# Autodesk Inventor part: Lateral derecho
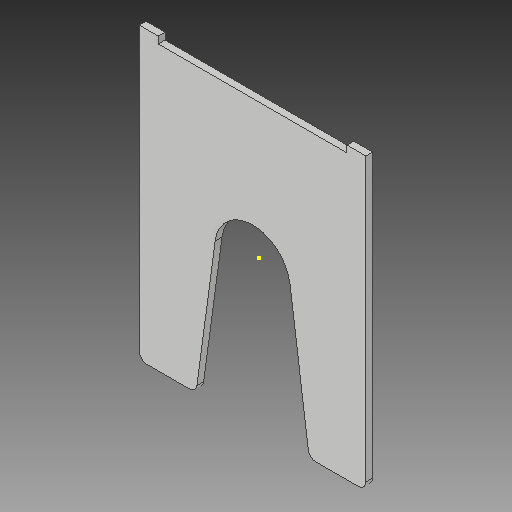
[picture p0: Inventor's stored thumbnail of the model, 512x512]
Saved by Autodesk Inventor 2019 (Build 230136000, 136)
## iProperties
Created: 2019-02
Part Number: Lateral derecho
Material: Genérico
Document SubType Name: Modeling
Designer: Juan Manuel Montalvo Navarrete
Density: 1 g/cm^3
Appearance: Valor por defecto
Author: Juan Manuel Montalvo Navarrete
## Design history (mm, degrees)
sketch "Boceto1"
  geometry: 1 further point
sketch "Boceto2"
  geometry: L1 (-250, 375)-(250, 375); L2 (300, 375)-(300, -355); L3 (-300, -355)-(-300, 375); L4 (-300, 375)-(300, -375); L5 (300, 375)-(-300, -375); L6 (-280, -375)-(-167.459, -375); L7 (280, -375)-(167.459, -375); L8 (-147.642, -357.701)-(-99.084, -1.493); L9 (99.084, -1.493)-(147.642, -357.701); L10 (-300, 375)-(-300, 393); L11 (-300, 393)-(-250, 393); L12 (-250, 393)-(-250, 375); L13 (300, 375)-(300, 393); L14 (300, 393)-(250, 393); L15 (250, 393)-(250, 375); A1 r 100 centre (0, -15) between (99.084, -1.493) and (-99.084, -1.493); A2 r 20 centre (-167.459, -355) between (-167.459, -375) and (-147.642, -357.701); A3 r 20 centre (-280, -355) between (-300, -355) and (-280, -375); A4 r 20 centre (167.459, -355) between (147.642, -357.701) and (167.459, -375); A5 r 20 centre (280, -355) between (280, -375) and (300, -355); 4 further points
  constraints: 30 end point, 10 point on circle, 10 point on line, 10 tangent, 5 centre point, 5 perpendicular, 3 equal radius, 3 horizontal, 2 collinear, 2 midpoint, 2 vertical, 1 parallel
  dimensions: "d1" = 150 distance of L5.end point (-150, -375); "d2" = 600 distance of L3.end L2.start; "d3" = 150 distance of L4.end point (150, -375); "d4" = 300 distance from line of L3 point (0, 725.354); "d5" = 100 radius of A1; "d6" = 360 vertical distance of L5.end A1.centre; "d7" = 20 radius of A2; "d8" = 18 distance of L3.end L10.end; "d9" = 50 distance of L10.end L11.end; "d10" = 18 distance of L2.start L13.end; "d11" = 50 distance of L13.end L14.end; "d12" = 750 distance between parallel lines of L7 L1; "d13" = 18 distance of L11.end L1.start
extrude "Extrusión1" new body sketch "Boceto2" distance "d14" = 18; taper "d15" = 0 deg
node "Sólido1"
